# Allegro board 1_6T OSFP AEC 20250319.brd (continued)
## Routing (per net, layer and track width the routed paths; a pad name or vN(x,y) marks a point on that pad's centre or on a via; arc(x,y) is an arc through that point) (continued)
PHY_SELF_INIT_33: length 11.8
  L11_GND w0.071: v6(6.36,43.35) 6.63,43.08 7.29,43.08 7.64,42.73 7.96,42.73 8.52,42.17 13.78,42.17 14.52,41.42 15.72,41.42 15.91,41.23 v6(16.23,41.23)
  BOTTOM w0.14: R849.1 7.37,43.22 7.24,43.35 v6(6.36,43.35)
PMIC_SCL: length 59.3
  TOP w0.14: v1(2.86,12.93) 3.49,12.93 U20.20
  L2_GND w0.071: v2(18.77,10.91) 17.47,12.21 14.96,12.21 14.22,12.95 v1(14.05,12.95) 7.12,12.95 6.55,12.39 5.55,12.39 5.18,12.75 3.04,12.75 v1(2.86,12.93)
  L9_SIG2 w0.074: v6(15.31,39.57) 15.31,39.42 16.43,38.31 16.74,38.31 17.26,37.78 17.26,37.24 17.66,36.83 17.84,36.83 18.34,36.34 18.34,33.65 18.99,33.01 18.99,30.19 20.01,29.17 20.01,19.09 17.75,16.82 17.75,13.02 19.02,11.74 19.02,11.31 18.77,11.06 v2(18.77,10.91)
  BOTTOM w0.14: v2(18.77,10.91) 17.59,12.09 14.13,12.09 12.83,13.39 12.83,14.25 R62.2 13.47,14.88 U37.E3
PMIC_SDA: length 57.5
  TOP w0.14: v1(2.87,13.33) 3.04,13.5 U20.19
  L2_GND w0.071: v9(18.59,11.76) 18.59,12.08 18.22,12.45 15.06,12.45 v1(14.02,13.5) 13.67,13.14 7.06,13.14 6.48,12.56 5.63,12.56 5.26,12.93 3.26,12.93 v1(2.87,13.33)
  L9_SIG2 w0.074: 18.71,11.64 v9(18.59,11.76) ; 18.71,11.64 v6(18.71,11.59) ; 18.71,11.64 18.71,11.64 17.55,12.81 17.55,16.96 19.81,19.21 19.81,29.1 18.81,30.09 18.81,32.87 18.11,33.57 18.11,36.29 17.74,36.66 17.56,36.66 16.57,37.65 16.27,37.65 16.05,37.86 16.05,38.43 15.09,39.4 v6(15.01,39.4)
  BOTTOM w0.14: U37.E2 13.82,14.72 13.7,14.6 R64.2 13.7,13.05 14.32,12.42 17.88,12.42 v6(18.71,11.59)
PMIC_SYNC1: length 3.9
  TOP w0.14: v12(3.07,14.59) 3.08,14.59 3.16,14.5 U20.17
  L6_PWR1 w0.076: v6(6.24,14.04) 5.68,14.59 3.08,14.59 v12(3.07,14.59)
PMIC_SYNC2: length 1
  BOTTOM w0.14: U21.17 6.7,14.54 6.87,14.36 R685.1
RXN1: length 8.3
  L11_GND w0.102: v6(4.26,10.17) arc(4.14,10.05) 4.09,9.87 4.09,8.33 arc(3.91,7.44) 3.41,6.68 3.41,6.68 arc(2.75,5.71) 2.53,4.56 2.53,4.03 arc(2.57,3.8) v6(2.7,3.61)
  BOTTOM w0.33: J1.28 v6(2.7,3.61)
RXN2: length 8
  TOP w0.33: J1.33 v1(3,3.61)
  L2_GND w0.102: v1(4.26,10.17) arc(4.14,10.04) 4.09,9.87 4.09,9.53 arc(3.99,8.64) 3.67,7.8 arc(3.08,6.27) 2.83,4.65 2.83,4.01 arc(2.88,3.79) v1(3,3.61)
RXN3: length 6.4
  L11_GND w0.102: v6(4.5,3.61) 4.44,3.66 arc(4.35,3.8) 4.32,3.97 4.32,4.68 arc(4.45,5.44) 4.85,6.1 5.12,6.41 arc(5.46,6.97) 5.62,7.6 arc(5.62,7.85) 5.61,8.1 arc(5.66,8.27) v6(5.79,8.39)
  BOTTOM w0.33: v6(4.5,3.61) J1.25
RXN4: length 6.2
  TOP w0.33: v1(4.8,3.61) J1.36
  L2_GND w0.102: v1(4.8,3.61) 4.8,3.61 arc(4.68,3.79) 4.63,4 4.63,4.9 arc(4.73,5.74) 5.01,6.53 5.46,7.45 arc(5.58,7.76) 5.62,8.09 arc(5.66,8.27) v1(5.79,8.39)
RXN5: length 8
  L11_GND w0.102: v6(6.3,3.61) 6.29,3.62 arc(6.17,3.8) 6.13,4.01 6.13,4.41 arc(6.25,5.52) 6.62,6.57 arc(7.01,7.68) 7.14,8.86 7.14,9.87 arc(7.18,10.05) v6(7.31,10.17)
  BOTTOM w0.33: J1.22 v6(6.3,3.61)
RXN6: length 7.9
  TOP w0.33: J1.39 v1(6.6,3.61)
  L2_GND w0.102: v1(7.31,10.17) arc(7.19,10.04) 7.14,9.87 7.14,8.5 arc(7.01,7.3) 6.7,6.13 arc(6.5,5.37) 6.44,4.59 6.44,3.98 arc(6.48,3.78) v1(6.6,3.61)
RXN7: length 6.2
  L11_GND w0.102: 8.83,8.39 v6(8.83,8.39) 8.76,8.32 arc(8.69,8.21) 8.67,8.1 8.67,6.97 arc(8.56,6.43) 8.3,5.96 arc(8.02,5.43) 7.92,4.84 7.92,3.98 arc(7.96,3.8) 8.06,3.64 v6(8.1,3.61)
  BOTTOM w0.33: J1.19 v6(8.1,3.61)
RXN8: length 6.1
  TOP w0.127: J1.42 8.4,2.49
  TOP w0.33: 8.4,2.49 v1(8.4,3.61)
  L2_GND w0.102: v1(8.4,3.61) arc(8.28,3.79) 8.24,4 8.24,4.58 arc(8.3,5.29) 8.48,5.99 arc(8.61,6.48) 8.66,6.98 8.66,8.09 arc(8.71,8.27) v1(8.83,8.39)
RXP1: length 8.3
  L11_GND w0.102: v6(2.1,3.61) arc(2.22,3.78) 2.26,3.99 2.26,4.56 arc(2.51,5.81) 3.22,6.87 arc(3.66,7.54) 3.82,8.33 3.82,9.87 arc(3.78,10.05) v6(3.65,10.17)
  BOTTOM w0.33: J1.29 v6(2.1,3.61)
RXP2: length 8
  TOP w0.127: J1.32 2.4,2.49
  TOP w0.33: 2.4,2.49 v1(2.4,3.61)
  L2_GND w0.102: v1(2.4,3.61) arc(2.52,3.79) 2.56,4.01 2.56,4.66 arc(2.82,6.33) 3.43,7.92 3.43,7.92 arc(3.72,8.7) 3.82,9.53 3.82,9.87 arc(3.78,10.04) v1(3.65,10.17)
RXP3: length 6.4
  L11_GND w0.102: v6(3.9,3.61) arc(4.01,3.77) 4.05,3.97 4.05,4.68 arc(4.2,5.53) 4.65,6.28 4.92,6.59 arc(5.21,7.06) 5.35,7.61 5.35,7.61 5.35,8.1 arc(5.3,8.27) v6(5.18,8.39)
  BOTTOM w0.33: v6(3.9,3.61) J1.26
RXP4: length 6.2
  TOP w0.33: v1(4.2,3.61) J1.35
  L2_GND w0.102: v1(4.2,3.61) 4.2,3.61 arc(4.32,3.79) 4.37,4 4.37,4.9 arc(4.47,5.8) 4.77,6.65 5.22,7.57 arc(5.31,7.83) 5.35,8.1 5.35,8.09 arc(5.3,8.27) v1(5.18,8.39)
RXP5: length 8
  L11_GND w0.102: v6(6.7,10.17) arc(6.82,10.05) 6.87,9.87 6.87,8.86 arc(6.75,7.74) 6.38,6.68 arc(5.99,5.58) 5.86,4.41 5.86,3.99 arc(5.82,3.78) v6(5.7,3.61)
  BOTTOM w0.33: J1.23 v6(5.7,3.61)
RXP6: length 7.9
  TOP w0.33: J1.38 v1(6,3.61)
  L2_GND w0.102: v1(6,3.61) 6,3.61 arc(6.12,3.79) 6.17,4.01 6.17,4.59 arc(6.24,5.41) 6.45,6.22 arc(6.75,7.35) 6.87,8.51 6.87,9.87 arc(6.83,10.04) v1(6.7,10.17)
RXP7: length 6.2
  L11_GND w0.102: v6(8.23,8.39) 8.31,8.31 arc(8.37,8.21) 8.4,8.1 8.4,6.97 arc(8.31,6.52) 8.08,6.12 arc(7.76,5.52) 7.65,4.84 7.65,3.98 arc(7.61,3.78) v6(7.5,3.61)
  BOTTOM w0.33: J1.20 v6(7.5,3.61)
RXP8: length 6.1
  TOP w0.33: J1.41 v1(7.8,3.61)
  L2_GND w0.102: v1(7.8,3.61) arc(7.92,3.79) 7.97,4.01 7.97,4.58 arc(8.03,5.34) 8.22,6.08 arc(8.34,6.53) 8.39,6.99 8.39,8.11 arc(8.35,8.27) v1(8.23,8.39)
SCK_SLV: length 21.4
  TOP w0.14: v2(3.21,38.33) 3.63,38.33 4.29,37.67 4.29,34.43 2.73,32.87 2.41,32.87 2.37,32.83 2.16,32.83 U46.2
  L11_GND w0.071: v2(3.21,38.33) 3.42,38.13 4.53,38.13 5.78,39.38 8.44,39.38 9.59,40.52 10.25,40.52 11.3,39.48 14.19,39.48 14.91,38.76 15.19,38.76 v6(15.31,38.87)
SCK_SLV_18: length 5.1
  TOP w0.14: U1.A15 3.86,29.66 v4(3.85,29.66)
  L4_SIG1 w0.074: v4(3.85,29.66) 3.58,29.39 2.93,29.39 2.68,29.64 2.68,30.67 1.92,31.43 1.92,32.43 1.71,32.64 v4(1.71,32.84)
SPI_OE_DSP_EEPROM: length 18
  L11_GND w0.071: v2(1.24,36.4) 2.51,36.4 3.47,37.36 4.7,37.36 6.11,38.76 13.88,38.76 14.29,38.36 14.3,38.36 14.81,37.84 16.02,37.84 17.13,38.95 v6(17.13,39.22)
SS_N_SLV: length 20.5
  TOP w0.14: U46.3 2.69,33.21 3.94,34.46 3.94,37.46 3.53,37.88 v2(3.21,37.88)
  L11_GND w0.071: v6(15.61,39.05) 15.61,38.77 15.41,38.57 14.85,38.57 14.12,39.3 11.2,39.3 10.15,40.35 9.66,40.35 8.51,39.2 5.95,39.2 4.62,37.88 v2(3.21,37.88)
SS_N_SLV1: length 21.4
  TOP w0.14: v3(17.9,27.47) 17.54,27.11 U1.AG10
  L3_GND w0.081: v3(17.9,27.47) 18.95,28.52 18.95,33.47 18.77,33.66 v9(18.77,33.83)
  L9_SIG2 w0.074: v8(18.77,34.13) v9(18.77,33.83)
  L11_GND w0.071: v8(18.77,34.13) 17.78,34.13 17.33,34.57 17.33,35.84 16.98,36.2 10.78,36.2 v6(10.15,35.57)
  BOTTOM w0.14: v6(10.15,35.57) 9.71,35.13 U47.B2
SS_N_SLV_18: length 14.7
  L3_GND w0.081: v3(4.98,28.61) 3.56,28.61 3.16,29.01 v4(3.16,29.72)
  L4_SIG1 w0.074: v8(1.55,33.22) 1.77,33.22 2.55,32.44 2.55,31.04 2.88,30.71 2.88,30 v4(3.16,29.72)
  L11_GND w0.071: v8(1.55,33.22) 1.55,33.5 2.32,34.27 6.35,34.27 7.15,35.07 v6(7.15,35.94)
  BOTTOM w0.14: U47.A1 v6(7.15,35.94)
SWCLK: length 24.4
  L4_SIG1 w0.074: v8(4.29,35.51) 4.29,35.5 ; 4.29,35.5 4.46,35.34 16.66,35.34 17.28,34.71 v6(17.64,34.71) ; 4.29,35.5 4.28,35.52
  L10_GND w0.081: v6(15.31,39.22) 15.31,38.75 15.18,38.61 15.18,37.73 15.58,37.33 15.85,37.33 16.16,37.03 16.16,36.31 16.42,36.05 16.7,36.05 17.3,35.45 17.3,35.08 17.64,34.74 v6(17.64,34.71)
  L11_GND w0.071: v6(5.36,36.63) 5.28,36.54 4.79,36.54 4.29,36.04 v8(4.29,35.51)
  BOTTOM w0.14: R5.2 5.52,36.78 v6(5.36,36.63) ; R6.2 17.18,34.87 17.34,34.71 v6(17.64,34.71) 17.64,34.5 18.36,33.78 J18.3
SWDIO: length 27.4
  L4_SIG1 w0.074: v8(4.61,35.86) 4.9,35.57 18.49,35.57 v6(19.17,34.88)
  L10_GND w0.081: v6(17.64,35.75) 17.17,36.23 16.77,36.23 16.77,36.23 16.52,36.23 16.38,36.37 16.38,37.1 15.96,37.52 15.65,37.52 15.4,37.76 15.4,38.54 15.61,38.75 v6(15.61,39.4)
  L11_GND w0.071: v8(4.61,35.86) 4.61,35.98 4.89,36.27 8.55,36.27 v6(8.74,36.07)
  BOTTOM w0.14: R4.2 17.23,35.77 R647.1 ; R3.1 v6(8.74,36.07) ; v6(17.64,35.75) 17.73,35.75 J18.2 19.17,34.88 v6(19.17,34.88)
TEMP_SENSOR: length 8.3
  TOP w0.14: R22.2 18.29,33.34 R25.1 C40.2 18.29,38.08 18.43,38.22 v9(18.49,38.22)
  L9_SIG2 w0.074: v9(18.49,38.22) 18.36,38.35 18.36,38.35 18.19,38.52 18.19,38.75 17.74,39.2 17.74,39.46 17.33,39.87 16.69,39.87 arc(16.45,39.84) v6(16.22,39.75)
TXN1: length 6.6
  TOP w0.33: J1.58 v1(18,3.61)
  L2_GND w0.102: v1(18,3.61) 18,3.61 arc(18.12,3.79) 18.17,4.01 18.17,4.6 arc(18.01,5.4) 17.56,6.09 arc(17.11,6.59) 16.73,7.13 arc(16.53,7.59) 16.48,8.09 arc(16.43,8.27) v1(16.31,8.39)
TXN2: length 6.4
  L11_GND w0.102: v6(17.7,3.61) 17.75,3.68 arc(17.83,3.84) 17.86,4.02 17.86,4.78 arc(17.86,4.78) 17.86,4.78 arc(17.6,6.08) 16.86,7.19 16.85,7.19 arc(16.58,7.61) 16.48,8.1 arc(16.46,8.21) 16.39,8.31 v6(16.31,8.39)
  BOTTOM w0.33: J1.3 v6(17.7,3.61)
TXN3: length 7.9
  TOP w0.33: J1.55 v1(16.2,3.61)
  L2_GND w0.102: v1(16.2,3.61) 16.2,3.61 arc(16.32,3.79) 16.36,4.01 16.36,4.39 arc(16.21,5.32) 15.76,6.15 arc(15.16,7.29) 14.96,8.56 14.96,9.63 arc(14.91,9.8) v1(14.79,9.92)
TXN4: length 7.8
  L11_GND w0.102: v6(15.9,3.61) arc(16.02,3.85) 16.06,4.12 16.06,4.94 arc(15.94,5.75) 15.58,6.49 arc(15.14,7.41) 14.96,8.42 14.96,9.61 arc(14.91,9.78) v6(14.79,9.92)
  BOTTOM w0.33: J1.6 v6(15.9,3.61)
TXN5: length 6.3
  TOP w0.33: J1.52 v1(14.4,3.61)
  L2_GND w0.102: v1(14.4,3.61) 14.4,3.61 arc(14.52,3.79) 14.57,4.01 14.57,4.48 arc(14.38,5.74) 13.85,6.91 arc(13.57,7.5) 13.44,8.13 arc(13.39,8.29) v1(13.26,8.39)
TXN6: length 6.2
  L11_GND w0.102: v6(13.26,8.39) 13.34,8.31 arc(13.41,8.21) 13.43,8.1 arc(13.56,7.24) 13.84,6.42 arc(14.15,5.48) 14.26,4.5 14.26,4.04 arc(14.23,3.85) 14.15,3.67 v6(14.1,3.61)
  BOTTOM w0.33: J1.9 v6(14.1,3.61)
TXN7: length 8
  TOP w0.33: J1.49 v1(12.6,3.61)
  L2_GND w0.102: v1(12.6,3.61) 12.6,3.61 arc(12.72,3.79) 12.77,4.01 12.77,4.38 arc(12.64,5.35) 12.26,6.25 12.26,6.25 arc(12.26,6.25) 12.26,6.26 12.26,6.26 arc(12,6.97) 11.91,7.72 11.91,9.89 arc(11.86,10.05) v1(11.74,10.17)
TXN8: length 7.9
  L11_GND w0.102: v6(12.3,3.61) arc(12.42,3.85) 12.46,4.12 12.46,5.21 arc(12.37,5.91) 12.17,6.58 arc(11.97,7.24) 11.91,7.91 11.91,9.86 arc(11.86,10.04) v6(11.74,10.17)
  BOTTOM w0.33: J1.12 v6(12.3,3.61)
TXP1: length 6.6
  TOP w0.33: J1.59 v1(18.6,3.61)
  L2_GND w0.102: v1(18.6,3.61) arc(18.48,3.79) 18.43,4.01 18.43,4.6 arc(18.26,5.51) 17.75,6.28 arc(17.32,6.75) 16.95,7.27 arc(16.79,7.66) 16.75,8.08 16.75,8.09 arc(16.79,8.27) v1(16.92,8.39)
TXP2: length 6.4
  L11_GND w0.102: v6(16.92,8.39) 16.84,8.32 arc(16.77,8.21) 16.75,8.1 arc(16.83,7.71) 17.05,7.38 17.05,7.38 arc(17.85,6.19) 18.13,4.78 18.13,4.02 arc(18.17,3.8) v6(18.3,3.61)
  BOTTOM w0.33: J1.2 v6(18.3,3.61)
TXP3: length 7.9
  TOP w0.33: J1.56 v1(16.8,3.61)
  L2_GND w0.102: v1(16.8,3.61) arc(16.68,3.79) 16.63,4.01 16.63,4.39 arc(16.47,5.4) 15.98,6.31 arc(15.41,7.37) 15.22,8.56 15.22,9.62 arc(15.27,9.79) v1(15.39,9.92)
TXP4: length 7.8
  L11_GND w0.102: v6(16.5,3.61) arc(16.37,3.85) 16.33,4.12 16.33,4.94 arc(16.19,5.83) 15.81,6.64 arc(15.39,7.49) 15.23,8.43 15.23,9.61 arc(15.27,9.78) v6(15.39,9.92)
  BOTTOM w0.33: J1.5 v6(16.5,3.61)
TXP5: length 6.3
  TOP w0.33: J1.53 v1(15,3.61)
  L2_GND w0.102: v1(13.87,8.39) arc(13.75,8.29) 13.71,8.14 arc(13.83,7.57) 14.08,7.05 arc(14.64,5.82) 14.83,4.48 14.83,4.01 arc(14.88,3.79) v1(15,3.61)
TXP6: length 6.2
  L11_GND w0.102: v6(13.87,8.39) 13.79,8.32 arc(13.73,8.21) 13.7,8.1 13.7,8.11 arc(13.82,7.3) 14.09,6.53 arc(14.42,5.54) 14.53,4.5 14.53,4.02 arc(14.57,3.8) v6(14.7,3.61)
  BOTTOM w0.33: J1.8 v6(14.7,3.61)
TXP7: length 8
  TOP w0.33: J1.50 v1(13.2,3.61)
  L2_GND w0.102: v1(12.35,10.17) arc(12.22,10.04) 12.18,9.87 12.18,7.72 arc(12.26,7.03) 12.5,6.38 arc(12.9,5.42) 13.03,4.38 13.03,4.01 arc(13.08,3.79) v1(13.2,3.61)
TXP8: length 7.9
  L11_GND w0.102: v6(12.9,3.61) arc(12.77,3.85) 12.73,4.12 12.73,5.21 arc(12.73,5.22) 12.73,5.22 arc(12.64,5.97) 12.42,6.69 arc(12.24,7.29) 12.18,7.91 12.18,9.86 arc(12.22,10.04) v6(12.35,10.17)
  BOTTOM w0.33: J1.11 v6(12.9,3.61)
VCAP: length 16.8
  L8_GND w0.254: v6(18.31,37.49) 19.63,37.49 19.94,37.8 19.94,41.65 v8(19.27,42.32)
  L11_GND w0.254: v6(12.53,44.57) 12.79,44.32 18.96,44.32 19.27,44.01 v8(19.27,42.32)
  BOTTOM w0.203: 17.56,38.09 17.45,38.2 17.45,38.22 17.25,38.42 17.23,38.42 U2.A9
  BOTTOM w0.254: v6(18.31,37.49) 18.16,37.49 17.56,38.09
VLXSMPS: length 1.8
  BOTTOM w0.203: 16.46,42.57 16.46,42.38 15.62,41.54 15.62,41.36 15.61,41.36 U2.T4
N16845549: length 1.6
  BOTTOM w0.127: R787.2 13.89,34.44 13.6,34.44 R760.1 13.35,34.44 12.88,34.44 Y2.5
N16845553: length 1.6
  BOTTOM w0.127: R788.2 13.88,34.82 arc(13.87,34.82) 13.87,34.82 13.61,34.82 R759.1 13.33,34.82 12.86,34.82 Y2.4
N17308149:
  vias: v6(9.63,33.55) v6(9.93,33.56) v6(12.48,33.44) v6(12.84,33.44)
N17319056: length 2.6
  TOP w0.14: U1.A14 3.43,29.11 3.15,29.39 1.8,29.39 1.6,29.59 R755.1
N17320165: length 4.7
  TOP w0.14: R718.1 2.83,22.58 v3(2.95,22.7)
  L3_GND w0.081: v3(4.98,24.61) 4.63,24.96 3.12,24.96 2.95,24.79 v3(2.95,22.7)
N17320275: length 2.4
  TOP w0.14: v1(18.02,26.33) 18.24,26.56 R719.1
  L2_GND w0.076: v1(18.02,26.33) 17.41,25.73 16.82,25.73 16.48,26.07 v1(16.48,26.11)
N17322132: length 4.4
  TOP w0.14: v1(2.99,23.65) R770.1 R771.1
  L2_GND w0.071: v1(2.99,23.65) 2.98,23.65 2.98,24.97 3.29,25.28 4.64,25.28 v1(4.98,25.61)
N17324604: length 3.7
  TOP w0.14: U1.A9 3.67,26.61 2.6,25.54 R767.1 R75.1
N17324668: length 33.8
  L3_GND w0.081: v8(0.91,42.5) 0.91,42 1.49,41.42 1.49,40.65 1.2,40.36 1.2,39.9 2.39,38.72 2.39,35.34 2.67,35.06 2.67,30.98 2.09,30.4 2.09,28.54 1.75,28.2 1.75,27.14 2.03,26.85 2.82,26.85 3.28,26.39 4.69,26.39 v3(4.98,26.11)
  L11_GND w0.071: v6(10.91,44.91) 10.8,45.01 7.35,45.01 6.95,45.41 2.51,45.41 0.7,43.59 0.7,42.71 v8(0.91,42.5)
  BOTTOM w0.14: R105.1 R411.1 10.86,44.95 v6(10.91,44.91)
N17332280: length 2.9
  TOP w0.076: 17.19,28.36 16.73,28.36 U1.AF12
  TOP w0.14: 17.19,28.36 17.38,28.55 17.38,28.95 18.26,29.82 R693.1
N17332314: length 2
  TOP w0.14: R694.1 2.44,27 3.02,27 3.63,27.61 U1.A11
N17340636: length 1.5
  TOP w0.14: R46.2 7.31,13.67 R629.2 6.99,13.72 6.71,14 U20.3
N17341552: length 1.3
  TOP w0.14: U26.23 15.68,12.11 arc(15.68,12.11) C501.1 R712.1
N17341615: length 1.9
  TOP w0.14: U26.2 17.28,13.5 17.51,13.27 R710.2
N17342760: length 1.5
  L11_GND w0.203: 14.49,15.72 v6(14.48,15.72) v6(13.99,15.72) v6(13.65,15.72)
  BOTTOM w0.196: U37.C1 v6(13.99,15.72) U37.C2 v6(13.65,15.72) U37.C3
N17421630: length 0.7
  BOTTOM w0.127: C651.1 14.92,34.45 14.65,34.45 R787.1
N17421668: length 0.6
  BOTTOM w0.127: R788.1 14.63,34.84 14.93,34.84 C650.1
N17477873: length 1.6
  BOTTOM w0.14: U32.9 11.33,13.1 R735.2 C939.1
N17495631:
  vias: v6(3.05,27.68) v6(3.05,27.32) v6(3.65,29.96) v6(3.65,29.59)
N17495710: length 1.6
  BOTTOM w0.127: Y1.5 2.59,29.98 2.59,30.31 R35.1 2.62,30.63 2.62,30.9 R789.2
N17495716: length 0.6
  BOTTOM w0.127: R789.1 2.61,31.66 2.61,31.91 C50.1
N17495751: length 1.5
  BOTTOM w0.127: R790.2 2.23,30.91 2.23,30.62 R36.1 2.21,30.36 2.21,29.95 Y1.4
N17495757: length 0.6
  BOTTOM w0.127: R790.1 2.23,31.65 2.23,31.92 C51.1
N17508857: length 3.5
  TOP w0.14: R690.1 v1(18.2,25.98)
  L2_GND w0.071: v1(18.2,25.98) 18.12,25.9 18.12,25.01 17.89,24.79 16.32,24.79 15.99,25.11 v1(15.98,25.11)
N17508860: length 4.3
  TOP w0.076: U1.B11 4.23,27.36 3.77,27.36 3.63,27.22
  TOP w0.14: 3.63,27.22 3.63,26.96 2.6,25.94 1.57,25.94 R691.1
N17522369: length 0.9
  TOP w0.14: U20.4 6.69,14.5 6.94,14.25 R618.2
N17525795: length 1.7
  TOP w0.14: R779.2 18.23,14.37 R711.2 16.87,13.99 U26.3
N17525820: length 0.9
  TOP w0.14: R748.2 17.71,14.5 U26.4
N17538591: length 0.7
  BOTTOM w0.14: U37.E1 R852.2
N17587354: length 3.7
  BOTTOM w0.14: U21.3 2.91,14.04 2.46,13.59 2.46,12.42 2.15,12.12 R778.2 2.16,11.89 R610.2
N17609312: length 27.6
  L10_GND w0.081: v6(15.31,40.27) 15.25,40.33 15.25,41.05 15.66,41.46 15.66,41.63 16.27,42.25 v8(16.27,43.13)
  L11_GND w0.071: v8(16.27,43.13) 16.27,43.29 15.95,43.62 12.66,43.62 11.09,45.19 7.56,45.19 7.14,45.6 2.35,45.6 0.52,43.78 0.52,39.1 1.36,38.27 1.4,38.27 1.57,38.1 1.57,38.06 1.61,38.02 v6(1.61,37.55)
N17609315: length 17.2
  L3_GND w0.081: v4(1.59,38.33) 1.59,38.98 v3(1.43,39.14)
  L4_SIG1 w0.074: v4(1.59,38.33) 2.16,38.33 2.3,38.47 v8(2.78,38.47)
  L11_GND w0.071: v8(2.78,38.47) 2.78,39.67 3.74,40.62 6.25,40.62 6.5,40.37 7.1,40.37 8.2,41.47 13.33,41.47 14.06,40.75 14.06,40.45 14.16,40.34 14.62,40.34 14.73,40.45 v6(15.01,40.45)
N17609318: length 16.8
  TOP w0.14: v4(2.61,38.9) 2.78,38.72 R11.1
  L4_SIG1 w0.074: v7(2.03,39.28) 2.41,38.9 v4(2.61,38.9)
  L10_GND w0.081: v8(3.86,40.99) 2.88,40.99 2.03,40.14 2.03,39.28 v7(2.03,39.28)
  L11_GND w0.071: v8(3.86,40.99) 4.05,40.8 6.32,40.8 6.57,40.55 6.94,40.55 8.04,41.65 13.48,41.65 14.34,40.8 v6(14.34,40.62)
  BOTTOM w0.14: U2.N1 v6(14.34,40.62)
N17609321: length 12.1
  L11_GND w0.071: v6(13.78,40.62) 13.19,41.21 9.47,41.21 8.29,40.03 6.18,40.03 6.04,40.17 v6(5.41,40.17)
  BOTTOM w0.14: U2.L1 14.12,40.27 v6(13.78,40.62) ; v6(5.41,40.17) 5.23,40.17 4.1,39.05 R12.1
N17614675: length 3.1
  BOTTOM w0.14: U2.R9 17.13,41.38 17.84,42.09 17.84,42.79 18,42.94 R841.1 R842.1
N17630589: length 1.9
  TOP w0.14: U1.A13 3.81,28.78 3.25,28.78 3,29.03 R829.1
N17630592: length 2.6
  TOP w0.14: R830.1 17.9,28.76 v1(17.72,28.57)
  L2_GND w0.071: v1(15.98,28.11) 16.41,28.54 17.69,28.54 v1(17.72,28.57)
N17634649: length 11.1
  L2_GND w0.071: v3(10.86,26.53) 10.86,27.73 v1(10.48,28.11)
  L3_GND w0.081: v3(10.86,26.53) 11.05,26.53 11.8,25.78 12.16,25.78 12.31,25.93 12.64,25.93 13.3,25.28 15.68,25.28 15.81,25.41 16.64,25.41 18.03,24.02 18.3,24.02 18.54,23.78 v3(18.54,23.5)
N17634729: length 11
  L2_GND w0.071: v1(10.48,28.61) 11.08,28 11.08,27.42 11.6,26.9 v3(11.6,26.56)
  L3_GND w0.081: v3(11.6,26.56) 11.96,26.56 12.25,26.27 12.66,26.27 12.82,26.43 13.11,26.43 13.8,25.73 14.08,25.73 14.74,26.39 15.2,26.39 15.91,25.68 16.63,25.68 17.51,24.8 18.35,24.8 v3(18.57,24.58)
N17634818: length 2.8
  TOP w0.076: U1.B9 4.23,26.36 3.82,26.36 3.59,26.13
  TOP w0.14: R764.1 2.61,25.15 3.59,26.13
N17634883: length 2.5
  L3_GND w0.081: v3(15.98,24.61) 16.88,24.61 17.77,23.72 17.81,23.72 v3(18.03,23.5)
N17635276: length 2.5
  TOP w0.076: 17.38,29.36 16.73,29.36 U1.AF15
  TOP w0.14: 17.38,29.36 18.42,30.4 R833.1
N17635432: length 2.6
  TOP w0.14: R834.1 18.48,31.04 18,30.57 18,30.38 17.23,29.61 U1.AG15
N17635549: length 1.4
  TOP w0.14: R835.1 3.82,30.46 U1.A17
N17635552: length 2
  TOP w0.076: 3.57,30.86 3.57,30.86 4.23,30.86 U1.B17
  TOP w0.14: R838.1 2.79,30.86 3.57,30.86
N17635615: length 2.2
  L2_GND w0.071: v1(4.48,29.61) 4.22,29.35 3.16,29.35 v1(2.63,29.88)
N17635680: length 3.2
  TOP w0.076: 17.33,30.67 17.33,30.5 17.19,30.36 16.73,30.36 U1.AF16
  TOP w0.14: R815.1 18.27,32.08 17.91,31.72 17.91,31.24 17.33,30.67
N17635747: length 3.1
  TOP w0.14: R837.1 18.78,32.07 18.23,31.52 18.23,31.18 17.7,30.66 17.7,30.51 17.31,30.11 U1.AG16
N17635816: length 2.7
  L2_GND w0.076: v1(18.31,27.13) 18.12,26.94 17.07,26.94 16.79,26.66 16.43,26.66 v1(15.98,27.11)
N17636368: length 2.3
  TOP w0.14: R766.1 2.46,24.6 U1.A8
N17636718: length 1.6
  TOP w0.14: U1.AG11 17.31,27.61 17.93,28.24 17.93,28.24 R758.1
N17636870: length 31.2
  TOP w0.14: R854.1 19.37,27.94 19.13,27.71 v1(18.29,27.71)
  L2_GND w0.071: v1(18.29,27.71) 18.29,28.85 18.58,29.14 18.58,29.47 17.55,30.5 v4(17.55,30.78)
  L4_SIG1 w0.074: v4(17.55,30.78) 18.03,31.26 18.03,33.13 16.26,34.9 3.72,34.9 3.43,34.61 3.43,31.77 3.73,31.46 4.55,31.46 4.81,31.2 4.81,30.3 5.28,29.82 5.28,29.35 5.15,29.22 5.15,28.79 v4(4.48,28.11)
N17689668: length 1.2
  BOTTOM w0.14: U21.2 3.03,13.54 2.84,13.35 R845.2
N17728804: length 0.8
  TOP w0.14: R608.2 6.3,12.01 5.9,11.62 C78.1
N17738812: length 0.6
  TOP w0.14: C492.1 R712.2
N17896792: length 3.5
  BOTTOM w0.14: U22.B1 6.93,41.35 7.17,41.11 7.17,40.13 7.41,39.9 8.73,39.9 8.9,40.07 R32.1
N17922824: length 20.7
  L3_GND w0.081: v3(4.98,31.61) 5.56,31.61 5.85,31.32 6.1,31.32 6.39,31.61 6.56,31.61 6.85,31.32 7.1,31.32 7.39,31.61 7.56,31.61 7.85,31.32 8.1,31.32 8.39,31.61 8.59,31.61 8.89,31.32 9.13,31.32 9.43,31.61 9.56,31.61 9.85,31.32 10.1,31.32 10.39,31.61 10.99,31.61 11.29,31.32 11.53,31.32 11.82,31.61 12.06,31.61 12.35,31.32 12.6,31.32 12.89,31.61 13.06,31.61 13.35,31.32 13.6,31.32 13.89,31.61 14.06,31.61 14.35,31.32 14.6,31.32 14.89,31.61 15.06,31.61 15.35,31.32 15.68,31.32 v3(15.98,31.61) 16.9,31.61 17.27,31.98 17.27,32.73 16.8,33.2 16.8,35.68 16.9,35.78 16.9,36.02 16.72,36.2 16.72,36.7 v3(17.28,37.27)
N17922836: length 20
  TOP w0.14: 17.41,36.29 TP4.1 17.06,36.29 v3(17,36.35)
  L3_GND w0.081: v3(17,36.35) 17.08,36.27 17.08,35.71 16.99,35.62 16.99,33.38 17.46,32.91 17.46,31.88 16.69,31.11 v3(15.98,31.11) 15.62,30.76 14.82,30.76 14.61,30.96 14.34,30.96 14.13,30.76 13.75,30.76 13.6,30.91 13.35,30.91 13.2,30.76 12.75,30.76 12.6,30.91 12.35,30.91 12.2,30.76 11.75,30.76 11.6,30.91 11.35,30.91 11.2,30.76 10.43,30.76 10.08,31.11 9.9,31.11 9.63,30.85 9.39,30.85 9.13,31.11 8.93,31.11 8.63,30.82 8.39,30.82 8.09,31.11 7.89,31.11 7.6,30.82 7.35,30.82 7.06,31.11 6.93,31.11 6.63,30.82 6.39,30.82 6.09,31.11 5.89,31.11 5.6,30.82 5.27,30.82 v3(4.98,31.11)

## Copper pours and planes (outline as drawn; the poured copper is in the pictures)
AVDDH_1P2 on BOTTOM: 18.76,25.01 18.18,25.01 18.12,24.95 18.12,21.1 17.13,20.1 17.13,18.91 17.18,18.85 17.97,18.85 17.99,18.88 17.99,19.22 18.08,19.3 19.57,19.3 19.57,20.45 19.51,20.5 18.93,20.5 18.8,20.62 18.8,24.97
AVDDH_1P2 on L9_SIG2: 5.83,26.37 15.76,26.37 16.83,25.3 16.83,19.49 16.98,19.33 18.52,19.33 18.69,19.5 18.69,21.37 19.59,22.28 19.59,27.7 19.37,27.92 18.71,27.92 18.26,28.36 18.26,30.82 17.92,31.17 5.98,31.17 5.83,31.02
AVDDLPLL_0P94 on BOTTOM: 9.46,27.26 11.52,27.26 11.52,26.5 11.16,26.5 11.06,26.39 11.06,24.39 11.11,24.34 11.39,24.34 11.47,24.26 11.47,23.24 11.53,23.18 12.13,23.18 12.23,23.08 12.23,22.41 12.23,21.45 12.04,21.26 9.72,21.26 9.66,21.32 9.66,23.11 9.88,23.32 9.88,23.32 9.88,26.41 9.79,26.5 9.46,26.5
AVDDLPLL_0P94 on L11_GND: 15.61,26.64 15.6,26.65 15.6,27.85 15.14,28.31 4.81,28.31 2.1,25.6 2.1,21.87 2.52,21.45 10.68,21.45 10.83,21.6 10.83,22.56 10.68,22.72 3.9,22.72 3.64,22.98 3.64,24.18 4.05,24.59 15.61,24.59 15.61,24.6
AVDDLPLLLINE_0P94 on BOTTOM: 11.57,31.78 11.57,30.97 9.38,30.97 9.38,31.78
AVDDLPLLLINE_0P94 on BOTTOM: 14.92,30.97 14.92,31.78 15.76,31.78 15.81,31.73 15.81,31.27 15.94,31.14 19.5,31.14 19.75,30.9 19.75,29.42 19.71,29.38 17.09,29.38 16.83,29.65 16.12,29.65 15.89,29.87 15.89,30.79 15.71,30.97
AVDDLPLLLINE_0P94 on L7_PWR2: 18.61,31.84 4.04,31.84 3.78,31.59 3.78,30.32 3.96,30.14 15.65,30.14 15.86,29.93 18.27,29.93 18.27,29.92 18.61,29.92 18.79,30.11 18.79,31.66
AVDDLTXRX_0P94 on TOP: 19.37,26.44 20.12,26.44 20.17,26.39 20.17,24 20.05,23.88 19.15,23.88 19.08,23.96 19.08,26.14
AVDDLTXRX_0P94 on L4_SIG1: 5.99,24.89 6.5,24.38 17.21,24.38 17.66,23.92 20.05,23.92 20.18,24.05 20.18,27.53 20.01,27.69 18.75,27.69 17.96,28.49 17.96,30.56 17.26,31.26 6.64,31.26 5.99,30.61
AVDDTXDRV_0P94 on BOTTOM: 13.41,23.46 13.4,23.46 13.4,24.15 13.46,24.21 14.06,24.21 14.12,24.14 14.12,23.73 14.2,23.65 14.88,23.65 14.97,23.55 14.97,22.25 15.21,22.02 15.41,22.02 15.5,21.93 15.5,21.33 15.42,21.25 13.54,21.25 13.41,21.38
AVDDTXDRV_0P94 on L11_GND: 16.67,31.77 18.86,29.58 18.86,25.3 19.06,25.1 19.06,21.37 18.93,21.24 13.63,21.24 13.55,21.31 13.55,22.69 13.58,22.71 15.2,22.71 15.4,22.71 16.8,22.71 16.95,22.86 16.95,24.26 16.78,24.44 15.99,24.44 15.94,24.49 15.94,28.38 15.61,28.7 7.33,28.7 7.12,28.91 7.12,31.5 7.39,31.77
GND on TOP: 4.71,25.61 16.92,25.61 17.54,24.99 17.89,24.99 18.05,25.15 18.05,25.46 18.18,25.59 18.78,25.59 18.81,25.57 18.81,24.99 18.73,24.91 18.29,24.91 18.19,24.81 18.19,24.33 18.29,24.24 18.73,24.24 18.76,24.21 18.76,23.93 18.71,23.88 17.81,23.88 17.64,23.71 17.64,23.16 16.21,21.72 3.52,21.72 3.54,21.74 3.54,23.75 3.39,23.91 2.4,23.91 2.3,23.8 2.3,22.45 0.92,22.45 0.92,25.01 1.08,25.18 1.43,25.18 1.59,25.33 1.92,25.33 1.92,24.64 1.94,24.62 2.6,24.62 3.75,25.76 4.56,25.76
GND on TOP: 11.62,19.51 11.62,18.51 11.56,18.45 9.09,18.45 9.05,18.49 9.05,19.51
GND on TOP: 10.01,21.6 10.01,21.03 9.93,20.96 7.27,20.96 7.23,21 7.23,21.56 7.28,21.6
GND on TOP: 3.68,17.01 3.85,16.84 3.85,16.21 3.87,16.19 5.7,16.19 5.86,16.35 5.86,16.35 5.94,16.43 5.94,17.02 5.97,17.06 6.95,17.06 7,17 7,16.74 7.05,16.69 8.19,16.69 8.27,16.62 8.27,16.59 8.27,16.58 8.27,15.94 8.2,15.87 5.96,15.87 5.88,15.8 5.88,14.88 4.14,14.88 4.14,15.8 4.06,15.88 3.3,15.88 3.3,16.33 3.09,16.53 2.57,16.53 2.44,16.66 0.69,16.66 0.6,16.75 0.6,17.48 0.67,17.55 2.54,17.55 3.08,17.01
GND on TOP: 1.13,18.67 2.45,18.67 2.53,18.6 2.53,17.74 1.06,17.74 1.06,18.6
GND on TOP: 13.44,17.86 13.44,16.84 11.96,16.84 11.96,17.86
GND on TOP: 8.57,16.89 8.55,16.87 7.3,16.87 7.3,17.86 8.57,17.86
GND on TOP: 1.46,54.69 19.24,54.69 19.24,49.92 20.39,47.92 20.39,31.39 2.37,31.39 2.37,31.34 2.25,31.22 2.25,29.83 2.26,29.82 2.26,29.74 2.18,29.66 1.94,29.66 1.85,29.75 1.85,29.92 1.8,29.97 1.31,29.97 1.23,30.06 1.23,31.52 1.33,31.62 2.55,31.62 2.6,31.68 2.6,32.3 2.65,32.34 2.65,34.04 2.62,34.07 2.15,34.07 1.94,33.86 1.92,33.86 1.64,34.14 1.29,34.14 1.26,34.17 1.26,34.89 1.12,35.03 0.41,35.03 0.3,35.13 0.3,36.93 0.4,37.03 2.36,37.03 2.55,37.22 2.55,38.15 2.44,38.27 1.12,38.27 1,38.14 1,37.78 0.94,37.71 0.47,37.71 0.3,37.88 0.3,47.92 1.46,49.92
GND on TOP: 18.78,27.41 19.9,27.41 19.96,27.35 19.96,26.87 19.3,26.87 19.13,26.7 19.13,26.47 19.07,26.41 18.7,26.41 18.69,26.42 18.69,27.32
GND on TOP: 13.37,21.57 13.37,20.98 13.32,20.93 11.7,20.93 11.64,20.98 11.64,21.57
GND on TOP: 18.24,19.01 19.57,19.01 19.78,19.23 19.78,20.67 19.58,20.87 19.58,22.31 19.67,22.4 20.14,22.4 20.3,22.24 20.3,17.95 20.16,17.81 18.24,17.81 18.11,17.94 18.11,18.88
GND on TOP: 0.3,11.84 4.58,11.84 5.17,11.24 5.97,11.24 6.55,11.82 14.63,11.82 14.88,11.58 15.79,11.58 16.14,11.22 16.98,11.22 17.53,11.77 19.34,11.77 20.23,10.88 20.23,10.41 19.66,10.17 19.43,9.6 19.43,3.16 1.74,3.16 1.59,3.32 1.32,3.32 1.27,3.36 1.27,9.6 1.03,10.17 0.46,10.41 0.3,10.41
GND on TOP: 16.59,17 17.5,17 18.03,17.53 20.03,17.53 20.15,17.41 20.15,16.6 20.02,16.47 17.73,16.47 17.14,15.88 16.46,15.88 16.3,15.72 16.3,14.84 14.56,14.84 14.56,15.85 14.55,15.86 13.36,15.86 13.32,15.9 12.31,15.9 12.2,16.01 12.2,16.56 13.85,16.56 13.85,16.97 14.31,16.97 14.31,16.24 14.37,16.18 14.8,16.18 14.88,16.11 16.31,16.11 16.54,16.34 16.54,16.96
GND on BOTTOM: 0.62,18.67 2.45,18.67 2.53,18.6 2.53,17.27 2.79,17.01 3.89,17.01 3.89,16.39 4.08,16.19 5.96,16.19 6.14,16.36 6.14,17.01 7.14,17.01 7.4,17.28 8.47,17.28 8.5,17.25 8.5,16.54 8.44,16.49 6.74,16.49 6.56,16.31 6.56,15.96 6.54,15.94 6.54,15.85 5.86,15.85 5.81,15.79 5.81,14.91 4.13,14.91 4.13,15.58 3.8,15.91 3.33,15.91 3.09,16.15 2.61,16.15 2.43,16.33 1.77,16.33 1.7,16.4 1.7,16.87 1.63,16.94 0.58,16.94 0.5,17.02 0.5,18.55
GND on BOTTOM: 4.45,28.12 4.18,28.12 4.1,28.04 4.1,27.56 3.92,27.38 3.72,27.38 3.72,26.08 3.84,25.97 4.59,25.97 4.65,26.03 4.65,26.59 4.74,26.68 5.15,26.68 5.2,26.73 5.2,27.11 5.16,27.15 4.68,27.15 4.5,27.33 4.5,28.07
GND on BOTTOM: 3.3,31.8 4.7,31.8 4.82,31.67 4.82,30.97 5,30.79 6.1,30.79 6.1,29.99 6.05,29.95 5.82,29.95 5.5,30.27 4.71,30.27 4.54,30.1 4.54,29.36 4.44,29.26 4.19,29.26 4.06,29.39 4.06,30.26 3.99,30.33 3.16,30.33 3.11,30.38 3.11,31.61
GND on BOTTOM: 9.05,19.61 9.99,19.61 10.04,19.56 10.04,18.44 10.02,18.42 9.05,18.42 9,18.47 9,19.56
GND on BOTTOM: 18.5,17.55 19.5,17.55 19.83,17.22 19.83,15.66 19.56,15.39 18.66,15.39 18.62,15.44 18.62,17.05 18.49,17.17 18.49,17.54
GND on BOTTOM: 9.36,28.71 11.75,28.71 11.75,27.51 10.74,27.51 10.73,27.53 10.73,27.91 10.65,27.99 10.17,27.99 10.12,27.94 10.12,27.51 9.36,27.51
GND on BOTTOM: 3.95,24.36 5.75,24.36 5.78,24.34 5.78,23.8 5.83,23.75 3.9,23.75 3.9,24.31
GND on BOTTOM: 1.46,54.69 19.24,54.69 19.24,49.92 20.39,47.92 20.39,45.04 20.3,44.94 18.26,44.94 18.26,45.84 18.08,46.02 4.53,46.02 4.26,45.75 4.26,45.03 3.67,44.44 3.15,44.44 2.94,44.23 2.13,44.23 1.91,44.02 0.38,44.02 0.3,44.1 0.3,47.92 1.46,49.92
GND on BOTTOM: 4.1,14.66 4.9,14.66 4.9,13.44 4.41,13.44 4.41,12.5 4.39,12.48 3.24,12.48 3.22,12.5 3.22,13.21 3.24,13.24 3.98,13.24 4.08,13.34 4.08,13.44 4.1,13.45
GND on BOTTOM: 5.14,14.66 5.92,14.66 5.92,13.7 6.75,13.7 6.77,13.68 6.77,12.62 6.67,12.51 6.16,12.51 6.11,12.55 6.11,13.18 5.85,13.44 5.14,13.44
GND on BOTTOM: 12.64,41.58 12.41,41.81 11.34,41.81 11.14,41.61 11.14,39.96 11.4,39.7 12.64,39.7
GND on BOTTOM: 13.14,24.24 13.2,24.18 13.2,21.39 12.58,21.39 12.51,21.47 12.51,23.47 11.72,23.47 11.67,23.52 11.67,24.18 11.72,24.24
GND on BOTTOM: 6.26,25.78 6.51,25.78 6.59,25.71 6.59,25.32 6.67,25.25 7.09,25.25 7.12,25.22 7.12,24.5 7.1,24.5 7.1,24.31 7.17,24.24 9.79,24.24 9.84,24.18 9.84,23.63 9.78,23.58 6.6,23.58 6.49,23.68 6.49,24.83 6.25,25.07 6.25,25.31 6.23,25.33 6.23,25.76
GND on BOTTOM: 0.84,32.88 1.57,32.88 1.72,32.73 1.72,29.4 2.26,28.85 2.26,27.49 1.89,27.12 1.67,27.12 1.18,26.63 1.18,24.19 1.3,24.19 1.48,24.01 1.97,24.01 2.15,23.84 2.15,23.56 2.25,23.45 6.01,23.45 6.08,23.39 6.08,22.87 6.02,22.81 0.91,22.81 0.53,23.19 0.53,28.54 0.95,28.94 1.1,29.5 0.95,30.06 0.53,30.46 0.53,32.58
GND on BOTTOM: 8.52,18.65 8.52,17.68 8.42,17.58 7.28,17.58 7.2,17.66 7.2,18.65
GND on BOTTOM: 7.49,37.83 6.65,37.83 6.36,37.54 5.94,37.54 5.94,35.69 6.11,35.51 6.61,35.51 6.77,35.67 6.77,36.49 6.93,36.65 6.93,37.27 7,37.35 7.49,37.35
GND on BOTTOM: outline of 114 points within 1.25,31.37 20.36,43.66
GND on BOTTOM: 13.86,25.25 14.63,25.25 14.66,25.22 14.66,24.77 14.96,24.47 14.96,23.86 14.94,23.84 14.32,23.84 14.28,23.88 14.28,24.18 14.28,24.19 14.28,24.36 14.22,24.43 13.93,24.43 13.86,24.5
GND on BOTTOM: 15.69,17.2 14.33,17.2 14.21,17.08 14.21,16.6 14.13,16.52 14.11,16.52 14.05,16.46 14.05,16 14.1,15.95 14.18,15.95 14.48,16.25 15.7,16.25 15.7,17.19
GND on BOTTOM: 7.22,14.01 7.95,14.01 8.08,13.88 8.08,12.78 7.97,12.67 7.22,12.67 7.16,12.73 7.16,13.95
GND on BOTTOM: 0.56,12.04 0.66,12.05 20.04,12.05 20.14,12.04 20.39,12.04 20.39,10.41 20.23,10.41 19.67,10.17 19.43,9.6 19.43,3.41 19.33,3.31 19.09,3.31 18.97,3.19 1.27,3.19 1.27,9.6 1.03,10.17 0.46,10.41 0.3,10.41 0.3,12.04
GND on BOTTOM: 15.91,27.25 17.16,27.25 17.31,27.09 17.31,26.82 17.56,26.57 18.81,26.57 18.93,26.69 18.93,27.18 19.08,27.33 20.02,27.33 20.22,27.12 20.22,21.08 20.02,20.88 19.07,20.88 19.07,25.07 18.89,25.26 17.94,25.26 17.83,25.15 17.83,23.95 17.39,23.51 16.79,23.51 16.63,23.35 16.63,22.55 16.44,22.36 15.24,22.36 15.24,23.46 15.36,23.58 16.01,23.58 16.57,24.14 16.57,24.78 16.35,25 16.35,25.26 16.43,25.34 17.14,25.34 17.37,25.58 17.37,26.23 17.11,26.5 16.04,26.5 15.86,26.67 15.86,27.19
GND on BOTTOM: 10.64,19.47 12.51,19.47 12.71,19.27 12.71,16.67 12.64,16.59 12.03,16.59 12,16.62 12,18.32 11.92,18.39 10.62,18.39 10.48,18.54 10.48,19.31
GND on L2_GND: 1.46,54.69 19.24,54.69 19.24,49.92 20.39,47.92 20.39,15.25 20.14,15.25 18.53,13.65 20.14,12.04 20.39,12.04 20.39,10.41 20.23,10.41 19.67,10.17 19.43,9.6 19.43,0.38 19.36,0.31 1.34,0.31 1.27,0.38 1.27,9.6 1.03,10.17 0.46,10.41 0.3,10.41 0.3,12.04 0.56,12.04 2.16,13.65 0.56,15.25 0.3,15.25 0.3,28.49 1.05,29.5 0.3,30.51 0.3,47.92 1.46,49.92 ; 1 cut-out
GND on L3_GND: 1.46,54.69 19.24,54.69 19.24,49.92 20.39,47.92 20.39,15.25 20.14,15.25 18.53,13.65 20.14,12.04 20.39,12.04 20.39,10.41 20.23,10.41 19.67,10.17 19.43,9.6 19.43,0.38 19.36,0.31 1.34,0.31 1.27,0.38 1.27,9.6 1.03,10.17 0.46,10.41 0.3,10.41 0.3,12.04 0.56,12.04 2.16,13.65 0.56,15.25 0.3,15.25 0.3,28.49 1.05,29.5 0.3,30.51 0.3,47.92 1.46,49.92 ; 4 cut-outs
GND on L4_SIG1: 1.46,54.69 19.24,54.69 19.24,49.92 20.39,47.92 20.39,15.25 20.14,15.25 18.53,13.65 20.14,12.04 20.39,12.04 20.39,10.41 20.23,10.41 19.67,10.17 19.43,9.6 19.43,0.38 19.36,0.31 1.34,0.31 1.27,0.38 1.27,9.6 1.03,10.17 0.46,10.41 0.3,10.41 0.3,12.04 0.56,12.04 2.16,13.65 0.56,15.25 0.3,15.25 0.3,28.49 1.05,29.5 0.3,30.51 0.3,47.92 1.46,49.92 ; 4 cut-outs
GND on L5_GND, L6_PWR1, L7_PWR2, L8_GND: 1.46,54.69 19.24,54.69 19.24,49.92 20.39,47.92 20.39,15.25 20.14,15.25 18.53,13.65 20.14,12.04 20.39,12.04 20.39,10.41 20.23,10.41 19.67,10.17 19.43,9.6 19.43,0.38 19.36,0.31 1.34,0.31 1.27,0.38 1.27,9.6 1.03,10.17 0.46,10.41 0.3,10.41 0.3,12.04 0.56,12.04 2.16,13.65 0.56,15.25 0.3,15.25 0.3,28.49 1.05,29.5 0.3,30.51 0.3,47.92 1.46,49.92
GND on L6_PWR1: 16.42,24.34 3.87,24.34 3.75,24.21 3.75,22.08 4,21.82 16.52,21.82 16.6,21.9 16.6,24.16
GND on L7_PWR2: 16.52,24.24 16.42,24.34 3.87,24.34 3.75,24.21 3.75,22.23 4.05,21.92 16.45,21.92 16.52,22
GND on L9_SIG2: outline of 148 points within 0.3,0.74 20.39,25.53
GND on L9_SIG2: 1.46,54.69 19.24,54.69 19.24,49.92 20.39,47.92 20.39,29.91 20.3,29.81 18.63,29.81 17.64,28.82 0.81,28.82 1.01,29.8 0.3,30.51 0.3,47.92 1.46,49.92
GND on L9_SIG2: 20.39,18.86 20.39,15.3 20.38,15.27 20.35,15.25 20.14,15.25 19.54,15.14 19.02,14.82 18.59,14.42 18.59,14.41 18.05,14.42 17.65,14.82 17.65,16.9 18.33,17.58 18.38,17.53 18.98,17.53 20.32,18.87 20.34,18.89 20.37,18.88 20.38,18.88
GND on L10_GND: 1.46,54.69 19.24,54.69 19.24,49.92 20.39,47.92 20.39,15.25 20.14,15.25 18.53,13.65 20.14,12.04 20.39,12.04 20.39,10.41 20.23,10.41 19.67,10.17 19.43,9.6 19.43,0.38 19.36,0.31 1.34,0.31 1.27,0.38 1.27,9.6 1.03,10.17 0.46,10.41 0.3,10.41 0.3,12.04 0.56,12.04 2.16,13.65 0.56,15.25 0.3,15.25 0.3,28.49 1.05,29.5 0.3,30.51 0.3,47.92 1.46,49.92 ; 1 cut-out
GND on L11_GND: 9.77,43.91 9.79,43.92 9.81,43.92 9.99,43.92 10.01,43.91 10.02,43.89 10.11,43.77 10.26,43.72 10.37,43.75 10.46,43.83 10.49,43.85 10.56,43.85 10.58,43.85 10.6,43.84 10.75,43.68 10.76,43.67 10.77,43.65 10.77,43.49 10.75,43.45 10.75,43.38 10.74,43.36 10.65,43.32 10.62,43.32 10.6,43.33 10.57,43.36 10.52,43.39 10.45,43.41 9.82,43.41 9.76,43.39 9.7,43.36 9.49,43.15 9.44,43.15 9.38,43.2 9.37,43.21 9.37,43.23 9.37,43.32 9.37,43.34 9.38,43.35 9.59,43.56 9.62,43.6 9.7,43.69 9.72,43.8 9.72,43.85
GND on L11_GND: 11.1,44.74 11.14,44.79 11.22,44.79 11.24,44.79 11.25,44.78 12.34,43.69 12.36,43.67 12.35,43.63 12.33,43.61 12.07,43.61 12.05,43.62 12.04,43.63 11.07,44.59 11.06,44.6 11.06,44.62 11.06,44.7
GND on L11_GND: 2.57,45.22 2.59,45.23 2.6,45.24 6.86,45.24 6.88,45.23 6.9,45.22 7.23,44.89 7.25,44.87 7.29,44.84 7.31,44.76 7.31,44.73 7.29,44.72 7.26,44.69 7.25,44.69 5.49,44.69 5.43,44.67 5.37,44.64 5.13,44.4 5.12,44.39 5.09,44.39 5.01,44.41 4.99,44.42 4.99,44.44 4.89,44.56 4.75,44.61 4.65,44.59 4.56,44.53 4.54,44.53 1.98,44.53 1.96,44.54 1.94,44.57 1.94,44.59
GND on L11_GND: 3.77,39.8 3.84,39.77 3.93,39.75 4.42,39.26 4.48,39.22 4.54,39.21 5.26,39.21 5.28,39.2 5.31,39.17 5.3,39.14 4.47,38.31 4.46,38.3 4.44,38.3 3.52,38.3 3.49,38.33 3.49,38.34 3.41,38.53 3.21,38.61 3.15,38.61 3.08,38.58 3.01,38.6 2.96,38.66 2.96,38.67 2.96,39.58 2.96,39.59 2.97,39.61 3.23,39.87 3.25,39.88 3.29,39.87 3.3,39.85 3.3,39.47 3.3,39.45 3.24,39.36 3.22,39.26 3.48,39.01 3.73,39.26 3.71,39.36 3.65,39.45 3.65,39.47 3.65,39.71 3.66,39.74 3.67,39.75 3.75,39.8
GND on L11_GND: 8.86,35.85 8.95,35.92 8.97,35.94 9.05,35.95 9.07,35.95 9.08,35.94 9.91,35.11 9.96,35.08 10.03,35.06 10.25,35.06 10.28,35.05 10.3,35.02 10.3,34.06 10.29,34.04 10.28,34.03 10.04,34.03 10.02,34.03 10.01,34.04 9.95,34.09 9.9,34.13 9.83,34.14 6.58,34.14 6.55,34.15 6.54,34.17 6.53,34.18 6.54,34.21 7.28,34.95 7.31,35.01 7.33,35.07 7.33,35.73 7.33,35.75 7.39,35.84 7.41,35.94 7.4,36.02 7.45,36.08 7.47,36.09 7.49,36.1 8.46,36.1 8.49,36.08 8.49,36.05 8.57,35.89 8.74,35.82
GND on L11_GND: 5.02,36.08 5.03,36.09 5.05,36.1 6.82,36.1 6.84,36.09 6.85,36.08 6.9,36.02 6.9,35.94 6.92,35.84 6.98,35.75 6.98,35.73 6.98,35.16 6.98,35.14 6.93,35.12 6.9,35.13 6.89,35.16 6.81,35.33 6.63,35.4 4.87,35.4 4.85,35.4 4.83,35.42 4.78,35.48 4.79,35.57 4.77,35.65 4.73,35.79 4.74,35.8
GND on L11_GND: 18.56,39.07 18.57,39.12 18.57,39.19 18.62,39.25 18.63,39.26 18.65,39.27 19.54,39.27 19.55,39.26 19.57,39.25 19.65,39.17 19.66,39.14 19.65,39.11 19.64,39.1 19.61,39.09 19.6,39.1 19.54,39.13 19.47,39.13 19.22,38.88 19.47,38.62 19.52,38.63 19.58,38.65 19.6,38.64 19.67,38.6 19.68,38.58 19.69,38.56 19.69,37.3 19.68,37.28 19.66,37.26 19.58,37.22 19.56,37.22 19.47,37.27 19.45,37.35 19.48,37.45 19.49,37.52 19.42,37.7 19.24,37.77 19.15,37.76 19.05,37.7 19.03,37.69 18.82,37.69 18.8,37.7 18.79,37.71 18.57,37.92 18.52,37.96 18.45,37.97 18.37,37.97 18.35,37.98 18.33,37.99 18.29,38.07 18.29,38.09 18.29,38.11 18.32,38.17 18.33,38.23 18.3,38.33 18.24,38.42 18.23,38.45 18.24,38.48 18.27,38.5 18.3,38.5 18.32,38.49 18.4,38.43 18.5,38.42 18.56,38.42 18.77,38.37 18.87,38.35 19.13,38.61 18.87,38.86 18.81,38.86 18.64,38.88 18.57,38.92 18.54,39
GND on L11_GND: 8.74,39.18 9.51,39.96 9.53,39.97 9.55,39.97 9.63,39.96 9.65,39.94 9.75,39.85 9.87,39.82 9.92,39.82 9.98,39.84 10.01,39.84 10.65,39.19 10.67,39.17 10.66,39.13 10.64,39.12 8.78,39.12 8.75,39.12 8.73,39.16
GND on L11_GND: outline of 121 points within 0.7,37.66 7.45,43.16
GND on L11_GND: outline of 100 points within 0.7,41.58 4.74,44.18
GND on L11_GND: outline of 83 points within 5.45,36.57 15.08,38.39
GND on L11_GND: 7.06,41.82 7.12,41.83 7.18,41.87 7.41,42.11 7.43,42.12 7.45,42.12 7.53,42.11 7.55,42.09 7.64,42.01 7.76,41.98 7.78,41.97 7.91,41.83 7.93,41.8 7.91,41.77 7.17,41.03 7.16,41.02 7.14,41.02 7.06,41.03 7.04,41.04 7.03,41.05 6.94,41.15 6.82,41.19 6.79,41.19 6.24,41.75 6.23,41.77 6.24,41.81 6.26,41.82
GND on L11_GND: 12.2,41.03 13.1,41.03 13.12,41.03 13.13,41.02 13.52,40.63 13.52,40.61 13.6,40.44 13.78,40.36 13.81,40.37 13.92,40.28 13.88,40.27 12.89,40.27 12.87,40.27 12.86,40.28 12.19,40.96 12.17,40.98 12.18,41.02
GND on L11_GND: 10.74,40.78 11.86,40.78 11.88,40.77 11.89,40.76 12.63,40.02 12.64,40 12.64,39.96 12.61,39.95 11.49,39.95 11.48,39.95 11.46,39.96 10.72,40.7 10.71,40.72 10.72,40.76
GND on L11_GND: outline of 378 points within 0.3,0.74 20.39,35.62
GND on L11_GND: 8.26,41.29 8.27,41.3 8.29,41.3 9.21,41.3 9.24,41.29 9.26,41.26 9.25,41.24 8.23,40.22 8.22,40.21 8.2,40.2 7.98,40.2 7.96,40.21 7.94,40.22 7.9,40.29 7.89,40.31 7.91,40.36 7.91,40.4 7.87,40.54 7.77,40.63 7.76,40.64 7.74,40.65 7.73,40.74 7.73,40.76 7.74,40.78
GND on L11_GND: outline of 126 points within 0.3,34.25 6.65,39.02
GND on L11_GND: outline of 171 points within 0.3,35 20.39,54.69
GND on L11_GND: 2.81,36.39 2.8,36.42 2.81,36.45 3.33,36.97 3.34,36.98 3.36,36.98 3.44,36.97 3.46,36.95 3.56,36.86 3.68,36.83 3.78,36.85 3.87,36.91 3.89,36.91 4.39,36.91 4.41,36.9 4.43,36.87 4.43,36.84 3.85,36.27 3.83,36.26 3.66,36.18 3.59,36.01 3.59,35.95 3.53,35.88 3.51,35.87 3.42,35.85 3.34,35.8 3.33,35.79 3.3,35.79 3.21,35.83 3.19,35.84 3.19,35.87 3.19,35.9 3.17,36.01 3.11,36.09
GND on L11_GND: 17.1,39.66 17.48,39.66 17.5,39.66 17.51,39.65 17.73,39.43 17.74,39.41 17.75,39.4 17.75,38.94 17.76,38.88 17.8,38.82 18.01,38.61 18.02,38.59 18.02,38.57 18,38.49 17.99,38.47 17.98,38.47 17.86,38.37 17.82,38.23 17.83,38.17 17.85,38.11 17.86,38.09 17.86,38.07 17.81,37.99 17.79,37.98 17.77,37.97 16.5,37.97 16.48,37.98 16.45,38.01 16.46,38.04 17.25,38.83 17.29,38.89 17.3,38.95 17.3,39 17.31,39.02 17.38,39.12 17.4,39.22 17.32,39.41 17.13,39.49 17.11,39.49 17.08,39.5 17.07,39.51 17.05,39.55 17.04,39.57 17.05,39.6 17.07,39.65
VCC_3V3 on TOP: 8.67,13.77 8.67,14.91 11.4,14.91 11.4,13.77
VCC_3V3 on BOTTOM: 1.31,34.12 4.47,34.12 5.53,33.07 7.03,33.07 7.03,34.48 6.88,34.63 6.11,34.63 5.16,35.58 5.16,37.86 6.03,38.73 9.51,38.73 9.71,38.53 9.71,38.04 10.31,38.04 10.61,37.74 11.71,37.74 11.96,38 11.96,39.19 11.79,39.36 11.01,39.36 10.65,39.72 5.55,39.72 4.18,38.35 4.18,35.82 3.95,35.59 3.01,35.59 2.93,35.51 2.55,35.51 2.53,35.49 2.53,35.26 2.43,35.16 1.33,35.16 1.24,35.07 1.24,34.19
VCC_3V3 on BOTTOM: 8.36,12.58 8.9,12.58 8.9,12.91 9.08,13.08 9.79,13.08 9.87,13.01 9.87,12.88 9.89,12.86 10.68,12.86 10.68,13.73 10.83,13.88 12.26,13.88 12.49,14.11 12.49,14.41 11.94,14.96 8.83,14.96 8.34,14.47 8.34,12.6
VCC_3V3 on BOTTOM: 1.94,26.6 1.17,26.6 1.17,26.21 1.16,26.2 1.16,24.27 1.17,24.26 2,24.26 2.07,24.33 2.07,26.47
VCC_3V3 on L7_PWR2: 11.58,12.6 9.41,12.6 8.85,12.04 3.6,12.04 2.26,13.38 2.25,13.94 2.03,14.67 1.34,15.32 1.22,15.4 0.59,15.4 0.43,15.56 0.43,17.11 0.57,17.25 10.79,17.25 11.58,16.46
VCC_3V3 on L9_SIG2: 0.43,15.56 0.43,28.22 1.25,29.05 1.25,30.04 0.53,30.77 0.53,37.56 0.77,37.8 2.07,37.8 2.25,37.62 2.25,34.07 2.81,33.51 2.81,27.39 2.5,27.08 2.5,24.12 2.89,23.73 2.89,22.36 2.25,21.71 2.25,19.41 2.64,19.02 2.64,15.57 2.47,15.4 0.58,15.4
VCC_3V3 on L10_GND: 2.64,15.52 2.52,15.4 0.5,15.4 0.34,15.56 0.34,26.29 0.61,26.56 1.77,26.56 1.97,26.35 1.97,21.74 2.64,21.07
VCC_OSFP on TOP: 10.99,1.35 10.99,3.05 10.96,3.08 10.96,11.79 11.11,11.93 11.11,12.23 11.04,12.3 9.47,12.3 9.37,12.19 9.37,12.01 9.69,11.69 9.69,4.89 9.86,4.71 9.86,3.3 9.92,3.24 9.99,3.14 10.01,3.02 10.01,1.33 10.1,1.25 10.89,1.25
VCC_OSFP on BOTTOM: 9.71,1.35 9.71,3.2 9.77,3.26 9.77,11.45 9.41,11.8 9.41,12.38 9.44,12.41 9.73,12.41 9.95,12.64 10.73,12.64 10.95,12.86 11.48,12.86 11.51,12.84 11.51,12.16 10.93,11.58 10.93,3.33 10.78,3.33 10.68,3.23 10.68,1.35 10.58,1.25 9.82,1.25
VCC_OSFP on L2_GND: 10.96,11.62 10.96,0.93 10.92,0.89 9.86,0.89 9.86,4.61 9.69,4.78 9.69,11.63 9.43,11.89 9.43,12.29 9.51,12.36 11,12.36 11.11,12.26 11.11,11.76
VCC_OSFP on L6_PWR1: 9.47,12.29 9.38,12.2 9.38,11.97 9.68,11.67 9.68,8.51 9.38,8.21 9.38,-3.09 10.93,-3.09 10.98,-3.04 10.98,9.66 10.91,9.73 10.91,11.6 11.2,11.9 11.2,12.22 11.14,12.29
VCC_OSFP on L7_PWR2: 9.39,12.21 9.39,11.95 9.67,11.67 9.67,8.11 9.16,7.6 9.16,-0.91 9.38,-1.13 9.38,-3.09 10.81,-3.09 10.98,-2.92 10.98,9.45 10.91,9.53 10.91,11.69 11.2,11.98 11.2,12.23 11.14,12.29 9.46,12.29
VCC_OSFP on L11_GND: 10.93,3.22 10.93,9.78 10.88,9.83 10.88,11.59 11.21,11.92 11.21,12.28 11.19,12.3 9.46,12.3 9.42,12.27 9.42,11.78 9.77,11.44 9.77,1.04 9.91,0.89 10.69,0.89 10.77,0.97 10.77,3.11 10.88,3.22
VDD_0P6 on TOP: 7.28,19.36 7.15,19.49 1.15,19.49 1.08,19.56 1.08,20.45 1.21,20.58 1.79,20.58 1.92,20.7 1.92,22.17 1.93,22.18 3.16,22.18 3.23,22.1 3.23,21.72 3.49,21.47 6.89,21.47 6.96,21.4 6.96,20.92 7.2,20.68 10.02,20.68 10.02,19.92 9.96,19.86 8.87,19.86 8.8,19.79 8.8,18.7 8.77,18.67 7.3,18.67 7.28,18.7
VDD_0P6 on BOTTOM: 6.01,29.75 5.66,29.75 5.66,29.75 5.48,29.75 5.4,29.83 4.86,29.83 4.84,29.82 4.84,29.36 4.97,29.23 5.28,29.23 5.32,29.19 5.32,29.01 5.37,28.96 6.01,28.96 6.04,28.99 6.04,29.72
VDD_0P6 on BOTTOM: 1.07,19.71 1.27,19.51 6.92,19.51 6.95,19.54 8.44,19.54 8.6,19.69 8.6,20.58 8.5,20.68 6.9,20.68 6.72,20.86 6.72,22.53 6.69,22.56 1.54,22.56 1.48,22.5 1.48,21.53 1.56,21.44 1.56,20.7 1.41,20.55 1.17,20.55 1.07,20.45
VDD_0P6 on L2_GND: 7.27,19.36 7.15,19.49 2.41,19.49 2.28,19.61 2.28,21.58 2.44,21.74 3.25,21.74 3.25,21.74 3.52,21.47 6.89,21.47 6.96,21.4 6.96,20.92 7.2,20.68 10.02,20.68 10.02,19.92 9.96,19.86 8.87,19.86 8.8,19.79 8.8,18.7 8.77,18.67 7.3,18.67 7.27,18.7
VDD_0P6 on L6_PWR1: 0.5,19.57 0.5,28.14 1.31,28.95 1.31,29.85 1.46,30 15.12,30 15.33,29.79 17.23,29.79 17.72,29.3 17.72,19.59 17.46,19.33 0.74,19.33
VDD_0P6 on L7_PWR2: 17.82,29.45 17.82,19.85 16.98,19.01 16.98,18.11 0.56,18.11 0.56,28.36 2.11,29.91 17.37,29.91
VDD_0P94 on L2_GND (solid shape): 19.84,23.54 19.84,22.59 19.23,21.98 19.23,20.29 18.94,19.99 18.34,19.99 17.85,19.5 11.98,19.5 11.66,19.83 10.36,19.83 10.23,19.96 10.23,20.81 10.36,20.94 11.26,20.94 11.5,20.69 13.79,20.69 14.56,21.46 17.38,21.46 18.86,22.93 18.86,23.48 19,23.62 19.77,23.62
VDD_0P94 on L3_GND (solid shape): 19.77,23.51 19.77,20.2 19.56,19.99 17.71,19.99 17.64,20.06 17.64,21.71 18.86,22.93 18.86,23.48 19,23.62 19.66,23.62
VDD_0P94 on L4_SIG1 (solid shape): 19.82,23.54 19.82,19.71 19.62,19.51 17.9,19.51 17.66,19.76 17.66,21.71 18.87,22.93 18.87,23.47 19.01,23.61 19.74,23.61
VDD_0P94 on TOP: 19.52,20.44 19.52,19.49 13.78,19.49 13.6,19.31 13.6,18.7 13.58,18.67 11.98,18.67 11.95,18.7 11.95,19.59 11.72,19.82 10.33,19.82 10.27,19.88 10.27,21.23 10.42,21.37 11.26,21.37 11.36,21.28 11.36,20.87 11.54,20.68 13.88,20.68 13.96,20.76 13.96,21.47 16.33,21.47 18.47,23.61 19.95,23.61 20.07,23.49 20.07,22.77 19.95,22.65 19.55,22.65 19.27,22.37 19.27,20.69
VDD_0P94 on BOTTOM: 19.7,28.16 19.7,28.95 19.64,29.01 18.72,29.01 18.62,28.91 18.62,28.16 18.74,28.03 19.57,28.03
VDD_0P94 on BOTTOM: 10.31,20.98 10.15,20.82 10.15,19.92 10.32,19.74 15.95,19.74 17.76,21.55 17.76,22.09 16.67,22.09 15.57,20.98
VDD_0P94 on L6_PWR1: 20.03,19.19 18.26,19.19 18.03,19.42 18.03,28.97 18.18,29.11 20.05,29.11 20.19,28.97 20.19,19.35
VDD_0P94 on L7_PWR2: 20.19,25.68 20.19,19.33 18.25,19.33 18.25,28.83 18.49,29.07 20.02,29.07 20.2,28.89 20.2,25.69
VDD_1P2 on BOTTOM: 18.25,18.17 17.92,18.5 13.41,18.5 13.25,18.34 13.25,17.46 13.35,17.35 13.72,17.35 14.09,17.72 15.94,17.72 16.33,17.33 16.33,14.14 16.6,13.87 17.38,13.87 18.25,14.75
VDD_1P8 on BOTTOM: 5.37,27.49 5.55,27.49 5.63,27.56 5.63,28.63 5.55,28.71 4.74,28.71 4.68,28.66 4.68,27.69 4.77,27.6 5.26,27.6
VDD_1P8 on BOTTOM: 15.33,28.76 15.33,27.51 16.8,27.51 16.8,28.27 15.79,28.27 15.79,28.76
VDD_1P8 on L3_GND: 15.71,29.14 5.7,29.14 5.29,28.73 5.29,27.46 5.55,27.21 15.71,27.21
VDD_1P8 on L9_SIG2: 3.84,31.43 3.92,31.35 5.04,31.35 5.27,31.12 5.27,28.96 5.6,28.63 5.6,28.02 3.64,28.02 3.03,28.63 3.03,33.53 2.4,34.17 2.4,41.4 2.4,41.4 2.4,42.67 2.5,42.77 3.03,42.77 3.24,42.98 3.24,43.54 3.34,43.63 3.74,43.63 3.84,43.53
VDD_3P3 on BOTTOM: 2.55,25.25 2.55,24.26 2.63,24.18 3.31,24.18 3.34,24.16 3.34,23.73 3.77,23.73 3.77,23.78 3.77,23.79 3.77,24.44 3.82,24.49 5.65,24.49 5.7,24.54 5.7,25.2 5.65,25.25 5.29,25.25 5.22,25.33 5.22,25.76 5.19,25.78 3.85,25.78 3.77,25.71 3.77,25.43 3.59,25.25
VDD_3P3 on BOTTOM: 15.29,23.91 15.29,25.12 15.4,25.23 16.06,25.23 16.09,25.2 16.09,24.77 16.12,24.74 16.29,24.74 16.32,24.72 16.32,24.27 15.97,23.91
VDD_3P3 on L9_SIG2: 15.58,26.17 15.91,25.84 15.91,24.85 15.51,24.44 3.49,24.44 3.29,24.24 2.7,24.24 2.7,25.96 2.91,26.17
VDD_3P3_ESD0 on BOTTOM: 5.63,26.22 5.63,26.39 5.56,26.46 4.98,26.46 4.89,26.37 4.89,26 4.91,25.98 5.28,25.98 5.4,25.86 5.4,25.45 5.45,25.4 6.03,25.4 6.06,25.43 6.06,25.78
VDD_3P3_ESD1 on BOTTOM: 15.81,25.45 15.4,25.45 15.3,25.56 15.3,25.71 15.35,25.76 15.86,25.76 15.91,25.81 15.91,26.22 15.96,26.27 17.06,26.27 17.13,26.19 17.13,25.63 17.06,25.56 15.91,25.56
VDDA on BOTTOM: 17.56,40.9 17.39,40.9 17.33,40.85 17.33,40.75 17.4,40.68 17.97,40.68 18.44,41.15 18.44,42.65 17.92,42.65 17.92,41.25
VDDEFUSE_0P94 on L10_GND: 10.12,30.05 10.12,28.81 10.35,28.58 15.58,28.58 16.07,28.09 16.07,25.75 17.15,24.67 17.15,22.94 17.27,22.82 17.46,22.82 17.5,22.87 17.5,24.87 16.39,25.98 16.39,28.6 15.37,29.62 11.4,29.62 10.75,30.27 10.34,30.27
VIN1 on TOP: 6.15,15.38 6.76,15.38 6.76,15.13 6.15,15.13 6.15,14.88 6.71,14.88 7,14.59 8.42,14.59 8.42,14.9 8.69,15.17 10.15,15.17 10.15,17.86 9.05,17.86 9.05,16.92 8.57,16.43 8.57,15.95 8.24,15.62 6.15,15.62
VIN1 on TOP: 3.89,15.63 3.89,14.88 1.93,14.88 1.31,15.5 0.59,15.5 0.52,15.57 0.52,16.27 0.53,16.28 2.92,16.28 2.97,16.23 2.97,15.71 3.06,15.63
VIN1 on L2_GND: 2.79,16.27 1.86,16.27 1.73,16.14 1.73,15.74 2.47,15.01 3.33,15.01 4.63,16.31 5.07,16.31 6.86,14.51 8.23,14.51 8.36,14.65 8.36,15.65 8.19,15.83 7.05,15.83 5.58,17.3 3.82,17.3
VIN2 on TOP: 16.56,15.63 17.25,15.63 17.85,16.22 20.13,16.22 20.13,15.57 20.03,15.47 19.41,15.47 18.82,14.88 16.56,14.88
VIN2 on TOP: 13.51,14.72 13.68,14.88 14.3,14.88 14.3,15.13 13.71,15.13 13.71,15.38 14.28,15.38 14.28,15.63 12.24,15.63 11.72,16.14 11.72,17.86 10.5,17.86 10.5,15.19 10.53,15.17 11.34,15.17 12.13,14.38 13.42,14.38 13.51,14.48
VIN2 on L2_GND: 13.58,14.38 15.33,16.13 15.33,16.16 16.34,16.16 17.51,14.99 18.15,14.99 18.74,15.59 18.74,16.11 18.64,16.22 17.86,16.22 16.7,17.38 14.62,17.38 12.89,15.65 12.33,15.65 12.2,15.52 12.2,14.5 12.33,14.38
VIN3 on BOTTOM: 13.07,15.23 11.42,15.23 11.4,15.25 11.4,16.01 10.63,16.78 10.63,17.89 10.71,17.97 11.7,17.97 11.88,17.79 12.54,17.79 12.78,17.55 12.78,16.43 13.13,16.09 13.13,15.28
VIN4 on BOTTOM: 3.89,15.66 3.89,14.94 3.86,14.91 3.22,14.91 3.07,14.76 2.02,14.76 1.23,15.55 0.58,15.55 0.52,15.61 0.52,16.31 0.53,16.33 1.3,16.33 1.75,15.88 2.99,15.88 3.2,15.66 3.89,15.66
VIN4 on BOTTOM: 7.01,14.68 8.12,14.68 8.56,15.12 8.72,15.28 9.48,15.28 10.05,15.84 10.05,17.93 9.98,17.99 8.81,17.99 8.81,16.5 8.62,16.31 7,16.31 6.93,16.25 6.93,15.84 6.75,15.66 6.14,15.66 6.14,14.91 6.78,14.91
VIN4 on L11_GND: 1.44,16.07 1.44,15.25 1.47,15.24 2,14.75 2.83,14.75 2.98,14.9 2.98,15.37 3.87,16.26 5.5,16.26 7.06,14.7 8.17,14.7 8.3,14.84 8.3,15.74 6.67,17.38 2.75,17.38
MCU33 on BOTTOM: 14.92,38.43 15.07,38.59 15.07,38.74 15.05,38.76 14.97,38.76 14.87,38.66 14.57,38.66 14.41,38.51 14.41,37.9 14.34,37.82 13.73,37.82 13.6,37.95 13.6,38.99 13.69,39.08 14.05,39.08 14.44,39.48 14.74,39.48 14.79,39.53 14.79,39.63 14.72,39.7 14.03,39.7 13.7,40.03 13.7,40.8 13.78,40.87 14.67,40.87 14.74,40.95 14.74,40.97 14.49,41.23 12.97,41.23 12.9,41.16 12.9,39.54 12.81,39.45 12.56,39.45 12.48,39.37 12.48,38.31 12.53,38.26 12.74,38.26 12.79,38.21 12.79,37.45 13.36,36.88 14.74,36.88 14.85,36.78 15.68,36.78 15.79,36.89 15.79,37.22 15.66,37.34 15.07,37.34 14.92,37.49
MCU33 on BOTTOM: 17.41,39.88 17.66,39.88 17.77,39.98 17.77,40.29 17.79,40.31 18.45,40.31 18.48,40.29 18.48,39.99 18.45,39.96 18.05,39.96 17.98,39.89 17.98,38.48 18.18,38.28 18.46,38.28 18.5,38.24 18.5,37.93 18.48,37.9 18.2,37.9 17.51,38.59 17.41,38.59 17.41,38.61 17.44,38.64 17.44,38.74 17.41,38.76 17.46,38.82 17.54,38.82 17.66,38.94 17.66,39.58 17.61,39.63 17.41,39.63 17.36,39.68 17.36,39.83
MCU33 on L6_PWR1: 17.55,39.19 18.22,38.51 18.22,38.08 17.81,37.67 17.81,36.96 17.57,36.71 15.24,36.71 14.95,37 14.95,42.12 15.13,42.3 16.18,42.3 16.37,42.12 16.37,40.36
VCAP on BOTTOM: 14.22,42.47 15.48,42.47 15.56,42.4 15.56,42.24 15.15,41.84 15.15,41.15 15.07,41.08 14.9,41.08 14.06,41.91 12.81,41.91 12.66,42.07 11.89,42.07 11.72,42.24 11.72,44.78 12.13,45.19 13.7,45.19 13.86,45.04 13.86,42.83
VCAP on BOTTOM: 18.48,37.67 18.17,37.67 17.87,37.98 17.59,37.98 17.59,37.91 17.99,37.51 17.99,36.85 18.17,36.68 19.06,36.68 19.06,37.04 18.99,37.11 18.6,37.11 18.48,37.24
VLXSMPS on BOTTOM: 15.53,41.61 15.53,41.13 15.56,41.1 15.68,41.1 15.71,41.13 15.71,41.51 15.99,41.79 16.32,41.79 16.65,42.12 16.65,43.29 15.37,44.56 15.37,45.16 15.35,45.19 14.42,45.19 14.39,45.15 14.39,43.46 14.56,43.29 15.98,43.29 16.19,43.08 16.19,42.27
N17308149 on L11_GND (solid shape): 12.98,33.68 12.98,33.38 12.92,33.32 9.53,33.32 9.44,33.41 9.44,33.72 9.5,33.77 12.89,33.77
